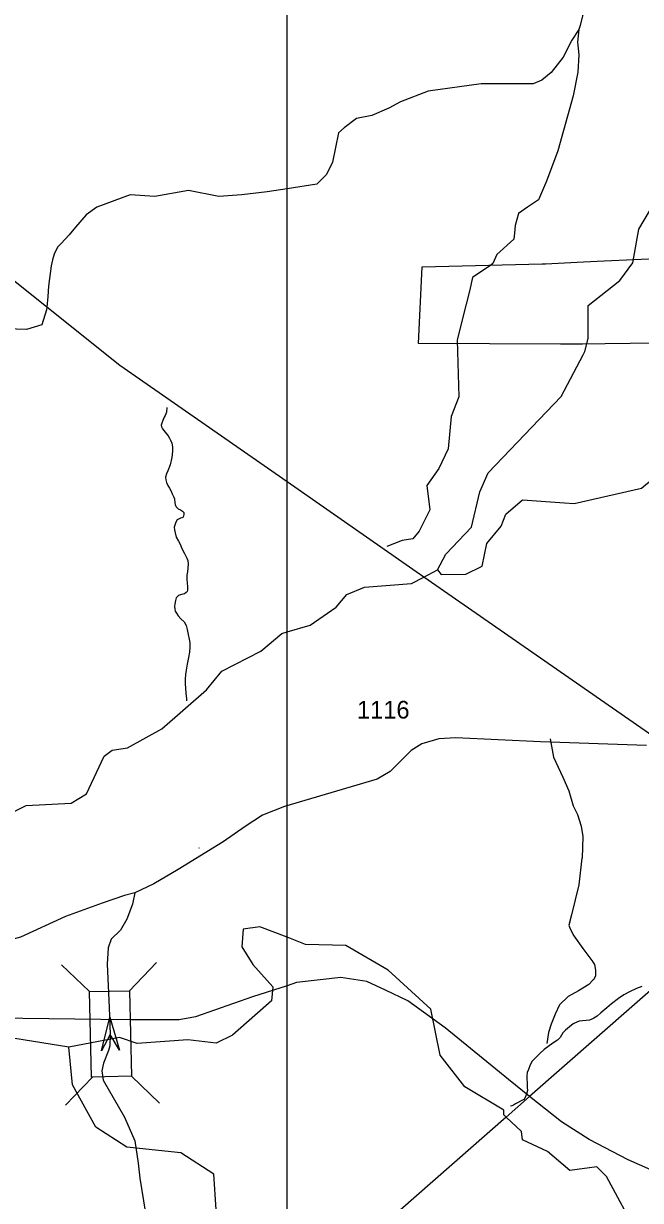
# Model space of a CAD drawing. Extents: x 2001466 to 2224147, y 644118 to 847247.
# Drawn here: x 2028046 to 2032407, y 668689 to 677010 of the extents above; entities that cross this region are included whole.
import ezdxf

# ---------------------------------------------------------------- set-up
doc = ezdxf.new("R2010")
doc.units = 0
for name, color, linetype in [('Exist Boundary Political City Limit New', 7, 'Continuous'), ('Exist Hydrographic Creek Single Shore', 7, 'Continuous'), ('Exist Hydrographic Misc Water Feature', 7, 'Continuous'), ('Exist Railroad Mainline', 7, 'Continuous'), ('Exist Road Non-System Type 51', 7, 'Continuous'), ('Exist Road Non-System Type 51 Label', 7, 'Continuous'), ('Exist Road Secondary Structure Standard Bridge Attributed CELL', 7, 'Continuous'), ('Exist Road Secondary Structure Standard Bridge CELL', 7, 'Continuous'), ('Exist Road Secondary Type 41 Attributed', 7, 'Continuous'), ('Exist Road Secondary Type 51 Attributed', 7, 'Continuous'), ('Exist Road Secondary Type 51 Number Label', 7, 'Continuous'), ('Exist Utilities Electrical Transmission Line', 7, 'Continuous'), ('Map Preparation Boundary City Limit Buffer Line', 7, 'Continuous'), ('Map Preparation Inset Cut Line', 7, 'Continuous')]:
    doc.layers.add(name, color=color, linetype=linetype)

msp = doc.modelspace()

# ---------------------------------------------------------------- linework, layer by layer
at = {"layer": 'Exist Boundary Political City Limit New'}
msp.add_lwpolyline([(2032542, 674748.9), (2032335.8, 674746.7), (2032158, 674745.7), (2031998.4, 674743.9), (2031841.6, 674743.9), (2030839, 674747.7), (2030863.5, 675289.1), (2031713.8, 675310.6), (2031719.9, 675310.9), (2031736.4, 675311.7), (2032004.8, 675324.8), (2032150.1, 675331.9), (2032570.6, 675351.3)], dxfattribs=at)
at = {"layer": 'Exist Hydrographic Creek Single Shore'}
msp.add_line((2030876.5, 673096.5), (2030972.6, 673148), dxfattribs=at)
for points in [[(2029908.9, 672708.5), (2030072.6, 672756.1), (2030256.8, 672883.7), (2030330.8, 672974.1), (2030456.7, 673024), (2030789.7, 673050), (2030876.5, 673096.5)], [(2026324.7, 671047.5), (2026774.6, 671172.8), (2027290.7, 671165.6), (2027773.6, 671296.8), (2027874.7, 671357.2), (2027915.7, 671405.6), (2028065.6, 671481.2), (2028382.6, 671497.8), (2028490.7, 671564.5), (2028615.7, 671831), (2028673.8, 671872.5), (2028781.6, 671890), (2029023.6, 672022.9), (2029339.8, 672298.6), (2029448.7, 672430.9), (2029723.6, 672573), (2029872.7, 672697.9), (2029908.9, 672708.5)], [(2029908.9, 670550), (2029715.6, 670624.2), (2029599.6, 670606.9), (2029590.6, 670482.4), (2029666.6, 670356.2), (2029807.7, 670199.1), (2029799.7, 670100.8), (2029524.5, 669857.1), (2029408.7, 669800.4), (2029207.5, 669824.2), (2028849.7, 669798.6), (2028724.6, 669840.5), (2028366.6, 669772.3)], [(2031457.2, 669278.5), (2031441.6, 669293.2), (2031441.6, 669326), (2031166.6, 669492.3), (2030991.7, 669715.7), (2030924.6, 670041.9), (2030624.6, 670317.1), (2030324.6, 670490.5), (2030040.6, 670499.4), (2029908.9, 670550)], [(2028366.6, 669772.3), (2027849.7, 669855), (2027474.6, 669839.6), (2027333.5, 669813)], [(2034758.5, 668061.1), (2034674.4, 668075.9), (2034591.6, 668159.6), (2034482.5, 668368.5), (2034391.4, 668452.4), (2034232.5, 668458.9), (2034116.5, 668375.9), (2034049.6, 668285.4), (2033991.6, 668250.5), (2033799.4, 668277.4), (2033716.6, 668236.4), (2033424.6, 668301.4), (2033074.6, 668324.9), (2032391.6, 668443.7), (2032166.6, 668858.5), (2032099.6, 668925.5), (2031908.5, 668899.8), (2031749.5, 669034.2), (2031574.6, 669116.6), (2031566.6, 669175.8), (2031457.2, 669278.5)]]:
    msp.add_lwpolyline(points, dxfattribs=at)
at = {"layer": 'Exist Hydrographic Misc Water Feature'}
for points in [[(2031871.5, 673621.6), (2031938.6, 673617.3), (2032413.7, 673725.7), (2032496.8, 673792.9), (2032730.7, 673817.7), (2033046.7, 673942.5), (2033188.6, 674057.8), (2033346.7, 674116.9), (2033588.7, 674266.2), (2033937.7, 674649.5), (2034112.8, 674750.9), (2034370.7, 675126.3), (2034529.6, 675326.5), (2034545.6, 675450.9), (2034928.7, 676076.4), (2035018.7, 676149.9)], [(2032001.4, 674668.6), (2032013.7, 674691.9), (2032038.7, 674783.3), (2032037.6, 675016.2), (2032262.8, 675192.1), (2032354.7, 675318.2), (2032395.7, 675556.9), (2032470.7, 675683.4), (2032612.8, 675782.2), (2032795.7, 675857.2), (2032895.8, 675933.9), (2032896.7, 675934.3)], [(2030972.6, 673148), (2031030.6, 673258.4), (2031213.7, 673448.2), (2031272.8, 673699.7), (2031330.6, 673833.1), (2031846.7, 674373.8), (2032001.4, 674668.6)], [(2029060.1, 674294.2), (2029058, 674261.4), (2029048.2, 674239.5), (2029040.2, 674225.7), (2029030.1, 674203.8), (2029024.2, 674183.4), (2029020.1, 674169.5), (2029022.1, 674158), (2029028.3, 674143.9), (2029048.2, 674119.7), (2029068.3, 674095.5), (2029078.5, 674077.2), (2029086.3, 674064), (2029093.9, 674043.3), (2029099.5, 674016.1), (2029100.5, 673985.7), (2029094.7, 673941.7), (2029082.6, 673890.2), (2029066.6, 673847.8), (2029056.8, 673825.9), (2029050.9, 673802.3), (2029052.9, 673784.1), (2029056.8, 673766), (2029066.8, 673743.7), (2029078.5, 673725.4), (2029089, 673703.8), (2029097.2, 673685.7), (2029105.2, 673669.9), (2029109.1, 673661.7), (2029113.2, 673648.4), (2029115.2, 673622.1), (2029119.1, 673609.8), (2029121.2, 673602.3), (2029125.3, 673592.4), (2029139.2, 673579.8), (2029155.2, 673570.5), (2029171.2, 673562), (2029177.2, 673556.1), (2029179.2, 673551.9), (2029179.6, 673541.3), (2029177.2, 673526.5), (2029171.4, 673518.5), (2029165.3, 673516.1), (2029155.2, 673512.2), (2029142.9, 673506.7), (2029133.3, 673500.3), (2029123.2, 673484.1), (2029115.4, 673463.8), (2029111.6, 673448.4), (2029113.2, 673431), (2029117.5, 673408), (2029125.7, 673378.3), (2029141.7, 673350.1), (2029155.6, 673324.4), (2029163.6, 673302.1), (2029183.9, 673263.9), (2029201.8, 673229.9), (2029207.9, 673212.6), (2029210, 673187.9), (2029205.9, 673133.9), (2029199.9, 673110.2), (2029200.1, 673096.3), (2029200.1, 673078.2), (2029202, 673054.4), (2029206.1, 673028.1), (2029206.1, 673008.4), (2029206.3, 673002.6), (2029204.2, 672994.5), (2029196.2, 672986.4), (2029184.1, 672978.5), (2029172.2, 672974.6), (2029156.3, 672970), (2029142.3, 672966.2), (2029134.3, 672959.8), (2029126.3, 672948.4), (2029120.4, 672929.7), (2029116.5, 672904.4), (2029114.4, 672890.5), (2029116.5, 672868.3), (2029118.5, 672856), (2029126.5, 672840.2), (2029138.6, 672821.9), (2029158.5, 672801.8), (2029180.7, 672780), (2029196.6, 672752.7), (2029202.6, 672724.6), (2029210.6, 672690), (2029217.2, 672657.1), (2029220.8, 672632.4), (2029220.8, 672600.4), (2029219, 672564.3), (2029212.8, 672528.4), (2029203, 672480.2), (2029195, 672438.5), (2029190.1, 672406.6), (2029189.3, 672374.7), (2029189.5, 672340.2), (2029191.3, 672310.6), (2029193.4, 672274.5), (2029197.5, 672234.2)], [(2030972.6, 673148), (2030997.6, 673114.7), (2031172.7, 673117.7), (2031289.6, 673174.4), (2031322.6, 673334.5), (2031422.7, 673457.1), (2031455.7, 673541.8), (2031572.8, 673641.2), (2031871.5, 673621.6)], [(2029197.5, 672234.2), (2029198.3, 672221.1)], [(2032416.4, 670201.9), (2032378.4, 670186.3), (2032330.3, 670164.3), (2032290.5, 670142.1), (2032252.3, 670115.8), (2032202.5, 670079.9), (2032168.7, 670049.4), (2032126.6, 670015.8), (2032100.8, 669991.8), (2032076.8, 669977.4), (2032062.9, 669969.5), (2032046.7, 669963.3), (2032024.7, 669961.3), (2031998.9, 669959.4), (2031974.9, 669955.8), (2031956.9, 669949.6), (2031932.7, 669936.9), (2031904.8, 669916.9), (2031876.9, 669893), (2031858.8, 669872.8), (2031841, 669841.2), (2031821.1, 669821.1), (2031795.3, 669805.2), (2031763.1, 669781.3), (2031727.4, 669754.9), (2031699.3, 669730.9), (2031671.4, 669705.2), (2031641.3, 669672.9), (2031627.5, 669647), (2031615.6, 669614.4), (2031607.4, 669592.5), (2031603.5, 669570.4), (2031603.5, 669550.7), (2031607.6, 669517), (2031607.6, 669503), (2031607.6, 669486.6), (2031607.9, 669467), (2031601.7, 669439.2), (2031589.8, 669410.7), (2031582, 669402.7)], [(2029908.9, 668244.7), (2029850.6, 668314.9), (2029458.5, 668549.3), (2029408.7, 668625.8), (2029391.6, 668875.4), (2029158.5, 669024.6), (2028775.7, 669065.1), (2028558.5, 669207.4), (2028391.6, 669506.1), (2028366.6, 669772.3)], [(2031582, 669402.7), (2031563.8, 669392.4), (2031533.8, 669376.6), (2031523.8, 669371), (2031510, 669362.3), (2031497.9, 669358.4), (2031488.5, 669355.4)]]:
    msp.add_lwpolyline(points, dxfattribs=at)
at = {"layer": 'Exist Railroad Mainline'}
for points in [[(2032641.4, 668835), (2032321.1, 668976.7), (2032044.8, 669120.1), (2031850.3, 669244.5), (2031623.5, 669424.4), (2031474, 669542.9), (2031026.2, 669908.3), (2030762.5, 670099.4), (2030605.4, 670175.2), (2030474.2, 670236.9), (2030290.4, 670265), (2029976, 670228.8), (2029908.9, 670207.1), (2029664.8, 670128.5), (2029262.9, 669987.2), (2029146.7, 669966.6), (2028810.7, 669966.6), (2028591.9, 669969.2)], [(2028591.9, 669969.2), (2027486.5, 669982.5), (2027238.6, 669985.5), (2026778.6, 669988.8), (2026434.7, 669993), (2026286.5, 669996.8), (2026087.1, 670033.3), (2025987.4, 670068.3), (2025822.4, 670148.2), (2025748.8, 670199)]]:
    msp.add_lwpolyline(points, dxfattribs=at)
at = {"layer": 'Exist Road Non-System Type 51'}
for points in [[(2032213.3, 677365.4), (2032038.7, 677156.2), (2031997.6, 677064.8), (2031980.8, 676996.9), (2031972.4, 676967.1)], [(2031972.4, 676967.1), (2031921.5, 676891.7), (2031862.1, 676772.3), (2031775.1, 676664.8), (2031710.3, 676610.7), (2031648.2, 676583.7), (2031281, 676583.7), (2030907, 676532.4), (2030711.3, 676456.8), (2030627.6, 676410.9), (2030507.4, 676359.5), (2030399.4, 676337.9), (2030313, 676273.1), (2030273.9, 676238), (2030230.7, 676030), (2030187.5, 675943.5), (2030118.6, 675873.3), (2029908.9, 675841)], [(2031972.4, 676967.1), (2031961.4, 676877.1), (2031972.2, 676789.1), (2031964.7, 676665), (2031932.7, 676499.5), (2031824, 676110.9), (2031743.2, 675895.9), (2031687.7, 675764.4), (2031609, 675711.2), (2031544.2, 675668), (2031522.6, 675581.6), (2031516.7, 675528.6)], [(2029908.9, 675841), (2029767.6, 675819.3), (2029589.4, 675797.7), (2029427.4, 675786.9), (2029211.4, 675830.1), (2028973.8, 675786.9), (2028801, 675797.7), (2028563.4, 675711.2), (2028489.1, 675657.2), (2028413.5, 675570.8), (2028369, 675516.8), (2028311.5, 675454.9), (2028285.9, 675428.2), (2028262.1, 675378.9), (2028250.5, 675338.9), (2028242, 675295.9), (2028223.7, 675152), (2028218.8, 675080.1), (2028210, 675005)], [(2031516.7, 675528.6), (2031511.8, 675484.3), (2031393, 675376.3), (2031364.2, 675314.3), (2031349.8, 675300.7), (2031220.2, 675214.2), (2031198.6, 675117), (2031152.8, 674933.5)], [(2028210, 675005), (2028207.7, 674986.2), (2028174.6, 674879.3), (2028066.6, 674846.9), (2027710.2, 674857.7)], [(2031152.8, 674933.5), (2031112.2, 674771.2), (2031123, 674371.4), (2031069, 674231), (2031047.4, 674004.1), (2030982.6, 673863.6), (2030896.2, 673744.8), (2030917.8, 673571.9), (2030842.2, 673420.6), (2030799, 673366.6), (2030723.4, 673355.8), (2030615.4, 673312.6)], [(2031769.2, 671951.5), (2031791.6, 671823.2), (2031857.9, 671682.5), (2031900.7, 671584), (2031931.3, 671477.6), (2031962.7, 671417.4), (2031987.7, 671335), (2032000.7, 671260.8), (2031994.9, 671108.9), (2031992.9, 671108.9), (2031972.6, 670919.1), (2031919.9, 670707.8), (2031905.4, 670654.1), (2031907.3, 670658), (2031901, 670634.2), (2031910.7, 670610), (2031936.1, 670559.6), (2032001, 670468.9), (2032069.9, 670376.1), (2032068, 670378.2), (2032083.7, 670355.8), (2032089.2, 670317.7), (2032088.7, 670277.7), (2032078.4, 670251.9), (2032070.3, 670246.1), (2032041.9, 670216.5), (2031969.4, 670171.3), (2031896.9, 670130.2), (2031834.2, 670072.9), (2031805.4, 670005.3), (2031776.6, 669935.6), (2031757.8, 669875.8), (2031746.8, 669798)]]:
    msp.add_lwpolyline(points, dxfattribs=at)
at = {"layer": 'Exist Road Non-System Type 51 Label'}
msp.add_line((2029286.5, 671183), (2029288.4, 671180.3), dxfattribs=at)
at = {"layer": 'Exist Road Secondary Structure Standard Bridge Attributed CELL'}
msp.add_lwpolyline([(2028598.4, 669747.5), (2028655.6, 669984.6), (2028724.6, 669750.7), (2028658.7, 669862.7)], close=True, dxfattribs=at)
at = {"layer": 'Exist Road Secondary Structure Standard Bridge CELL'}
for p, q in [((2028313.8, 670355.5), (2028513.5, 670165)), ((2028986.3, 670371.3), (2028795.8, 670171.6)), ((2028532.8, 669560.9), (2028342.3, 669361.2)), ((2028808.7, 669567.3), (2029008.3, 669376.8))]:
    msp.add_line(p, q, dxfattribs=at)
msp.add_lwpolyline([(2028795.8, 670171.6), (2028810, 669567.4), (2028527.7, 669560.7), (2028513.5, 670165)], close=True, dxfattribs=at)
at = {"layer": 'Exist Road Secondary Type 41 Attributed'}
for points in [[(2028833.2, 670864.5), (2028817.4, 670784.2), (2028777.3, 670676.5), (2028732.9, 670600.4), (2028665.4, 670534.9), (2028644.3, 670473.7), (2028637.9, 670359.6), (2028650.6, 670053.4), (2028658.7, 669862.7)], [(2028658.7, 669862.7), (2028656.5, 669782), (2028647.7, 669748.3), (2028612.5, 669658.8), (2028600.8, 669604.6), (2028609.6, 669540), (2028760.4, 669277.9), (2028832.2, 669111), (2028857.5, 668952.5), (2028868.1, 668846.9), (2028905, 668612.4)]]:
    msp.add_lwpolyline(points, dxfattribs=at)
at = {"layer": 'Exist Road Secondary Type 51 Attributed'}
for points in [[(2032449.7, 671906.1), (2031701.3, 671931.4), (2031101.7, 671958.9), (2030981.4, 671952.5), (2030861.1, 671916.6), (2030786.1, 671870.2), (2030638.3, 671722.3), (2030545.4, 671667.3), (2029891, 671473), (2029734.7, 671413.8), (2029613.3, 671333.5), (2029457.1, 671223.7), (2029140.4, 671029.3), (2028967.3, 670927.9), (2028833.2, 670864.5)], [(2028833.2, 670864.5), (2028759.3, 670845.5), (2028603.1, 670790.6), (2028343.4, 670695.5), (2028025.7, 670549.7), (2027930.7, 670524.4), (2027854.7, 670522.3), (2027620.3, 670562.4), (2027445.1, 670570.8), (2027269.9, 670537), (2026703, 670389.2), (2026259.6, 670281.4), (2025995.7, 670215.9), (2025894.4, 670199), (2025750.3, 670203.2)]]:
    msp.add_lwpolyline(points, dxfattribs=at)
at = {"layer": 'Exist Utilities Electrical Transmission Line'}
for p, q in [((2030876.5, 673096.5), (2029908.9, 673769.8)), ((2033639.2, 671192.9), (2031623.5, 669424.4)), ((2031623.5, 669424.4), (2031457.2, 669278.5)), ((2031457.2, 669278.5), (2030056.5, 668049.7))]:
    msp.add_line(p, q, dxfattribs=at)
for points in [[(2028210, 675005), (2027012.9, 675961.3), (2025734.6, 676958.5)], [(2029908.9, 673769.8), (2028726.1, 674592.6), (2028210, 675005)], [(2032563, 671924.3), (2032494.6, 671970.8), (2030876.5, 673096.5)]]:
    msp.add_lwpolyline(points, dxfattribs=at)
at = {"layer": 'Map Preparation Boundary City Limit Buffer Line'}
msp.add_lwpolyline([(2032542, 674748.9), (2032335.8, 674746.7), (2032158, 674745.7), (2031998.4, 674743.9), (2031841.6, 674743.9), (2030839, 674747.7), (2030863.5, 675289.1), (2031713.8, 675310.6), (2031719.9, 675310.9), (2031736.4, 675311.7), (2032004.8, 675324.8), (2032150.1, 675331.9), (2032570.6, 675351.3)], dxfattribs=at)
at = {"layer": 'Map Preparation Inset Cut Line'}
for p, q in [((2029908.9, 675841), (2029908.9, 678148.2)), ((2029908.9, 673769.8), (2029908.9, 675841)), ((2029908.9, 672708.5), (2029908.9, 673769.8)), ((2029908.9, 671498.1), (2029908.9, 672708.5)), ((2029908.9, 670550), (2029908.9, 671498.1)), ((2029908.9, 670207.1), (2029908.9, 670550)), ((2029908.9, 668244.7), (2029908.9, 670207.1))]:
    msp.add_line(p, q, dxfattribs=at)

# ---------------------------------------------------------------- texts
at = {"layer": 'Exist Road Secondary Type 51 Number Label'}
msp.add_text('1116', height=125, dxfattribs=at).set_placement((2030403.3, 672096))

doc.saveas('drawing.dxf')
